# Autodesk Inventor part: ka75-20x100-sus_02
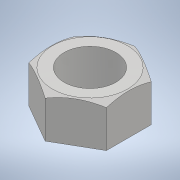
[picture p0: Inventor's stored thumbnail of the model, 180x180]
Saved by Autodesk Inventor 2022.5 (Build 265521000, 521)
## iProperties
Part Number: ka75-20x100-sus_02
Material: 一般
Document SubType Name: Modeling
Designer: ImaoCorp
Density: 1 g/cm^3
Appearance: 既定
Author: ImaoCorp
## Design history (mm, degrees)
feature "ka75-20x100-sus_02"
node "ソリッド1"
